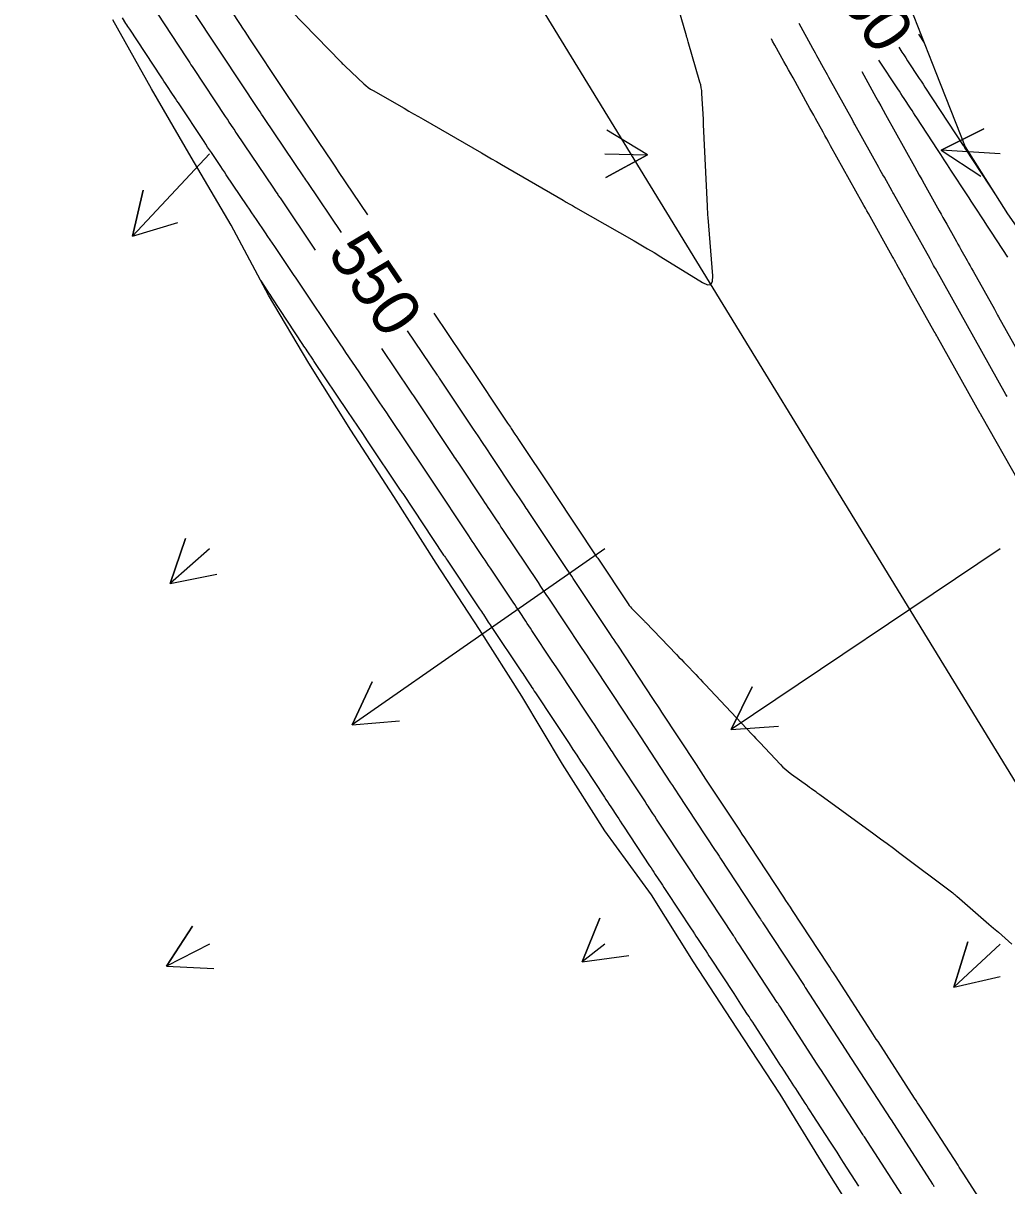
# Model space of a CAD drawing. Extents: x 954385 to 988206, y 1868364 to 1924553.
# Drawn here: x 956633.6 to 956758, y 1921488.4 to 1921635.4 of the extents above; entities that cross this region are included whole.
import ezdxf

# ---------------------------------------------------------------- set-up
doc = ezdxf.new("R2010")
doc.units = 0
for name, color, linetype in [('24', 7, 'Continuous'), ('26', 7, 'Continuous'), ('5', 7, 'Continuous'), ('6', 7, 'Continuous'), ('7', 7, 'Continuous'), ('Default', 7, 'Continuous')]:
    doc.layers.add(name, color=color, linetype=linetype)

msp = doc.modelspace()

# ---------------------------------------------------------------- linework, layer by layer
at = {"layer": '24'}
for points in [[(956745.29, 1921638.69), (956748.99, 1921629.23), (956752.71, 1921619.79), (956758.06, 1921611.33), (956763.82, 1921603.14), (956769.47, 1921594.87), (956775.07, 1921586.57), (956780.57, 1921578.22), (956785.99, 1921569.8), (956791.41, 1921561.4), (956796.82, 1921552.99), (956802.23, 1921544.58), (956807.33, 1921535.97), (956812.17, 1921527.21), (956816.87, 1921518.36), (956821.43, 1921509.43), (956826.18, 1921500.61), (956831.07, 1921491.88), (956835.81, 1921483.05)], [(956739.85, 1921482.96), (956734.55, 1921491.44), (956729.33, 1921499.97), (956723.81, 1921508.32), (956718.33, 1921516.69), (956713.03, 1921525.16), (956707.13, 1921533.28), (956701.77, 1921541.72), (956696.62, 1921550.29), (956691.27, 1921558.74), (956685.8, 1921567.12), (956680.43, 1921575.56), (956675.02, 1921583.97), (956669.7, 1921592.44), (956664.58, 1921601.03), (956659.88, 1921609.88), (956654.82, 1921618.5), (956649.77, 1921627.14), (956644.89, 1921635.87)]]:
    msp.add_lwpolyline(points, dxfattribs=at)
at = {"layer": '26'}
for points in [[(956707.13, 1921618.93), (956712.53, 1921618.8), (956707.27, 1921615.92), (956712.53, 1921618.8), (956707.4, 1921621.92)], [(956757.13, 1921618.93), (956749.68, 1921619.4), (956755.06, 1921622.07), (956749.68, 1921619.4), (956754.68, 1921616.08)], [(956657.13, 1921618.93), (956647.38, 1921608.5), (956648.73, 1921614.34), (956647.38, 1921608.5), (956653.12, 1921610.24)], [(956657.13, 1921568.93), (956652.17, 1921564.58), (956654.1, 1921570.26), (956652.17, 1921564.58), (956658.06, 1921565.75)], [(956707.13, 1921568.93), (956675.17, 1921546.69), (956677.72, 1921552.12), (956675.17, 1921546.69), (956681.15, 1921547.2)], [(956757.13, 1921568.93), (956723.12, 1921546.11), (956725.76, 1921551.5), (956723.12, 1921546.11), (956729.1, 1921546.52)], [(956707.13, 1921518.93), (956704.25, 1921516.68), (956706.5, 1921522.24), (956704.25, 1921516.68), (956710.19, 1921517.51)], [(956657.13, 1921518.93), (956651.69, 1921516.16), (956654.97, 1921521.19), (956651.69, 1921516.16), (956657.69, 1921515.84)], [(956757.13, 1921518.93), (956751.28, 1921513.49), (956753.04, 1921519.22), (956751.28, 1921513.49), (956757.13, 1921514.83)]]:
    msp.add_lwpolyline(points, dxfattribs=at)
at = {"layer": '6'}
for points in [[(956673.82, 1921608.96), (956669.56, 1921615.28), (956669.44, 1921615.47), (956669.31, 1921615.65), (956669.19, 1921615.83), (956669.07, 1921616.02), (956664.1, 1921623.38), (956663.91, 1921623.66), (956663.72, 1921623.95), (956663.53, 1921624.24), (956663.34, 1921624.52), (956658.69, 1921631.53), (956658.44, 1921631.91), (956658.19, 1921632.29), (956657.94, 1921632.67), (956657.69, 1921633.05), (956653.29, 1921639.72)], [(956758.02, 1921588.2), (956757.87, 1921588.46), (956748.95, 1921604.4), (956748.84, 1921604.6), (956748.72, 1921604.81), (956748.44, 1921605.31), (956748.27, 1921605.62), (956743.63, 1921613.92), (956743.57, 1921614.01), (956743.51, 1921614.13), (956743.47, 1921614.19), (956742.49, 1921615.96), (956742.32, 1921616.27), (956742.15, 1921616.57), (956741.98, 1921616.87), (956741.81, 1921617.18), (956738.76, 1921622.64), (956738.69, 1921622.76), (956738.62, 1921622.89), (956738.56, 1921623.01), (956738.49, 1921623.14), (956735.47, 1921628.59), (956735.3, 1921628.9), (956735.13, 1921629.2), (956734.96, 1921629.51), (956734.79, 1921629.82), (956734.12, 1921631.04), (956733.95, 1921631.34), (956733.78, 1921631.65), (956733.61, 1921631.95), (956733.44, 1921632.26), (956731.7, 1921635.41)], [(956744.32, 1921632.4), (956744.71, 1921631.8), (956744.96, 1921631.43), (956745.2, 1921631.06), (956745.44, 1921630.69), (956745.69, 1921630.32), (956746.66, 1921628.84), (956746.9, 1921628.47), (956747.15, 1921628.1), (956747.39, 1921627.73), (956747.63, 1921627.36), (956752.46, 1921619.98), (956752.53, 1921619.88), (956752.61, 1921619.75), (956752.65, 1921619.69), (956752.75, 1921619.53), (956752.77, 1921619.51), (956756.7, 1921613.49)], [(956757.28, 1921482.49), (956752.45, 1921489.97), (956752.29, 1921490.22), (956752.13, 1921490.47), (956751.97, 1921490.72), (956751.81, 1921490.97), (956747.07, 1921498.29), (956746.88, 1921498.58), (956746.69, 1921498.87), (956746.51, 1921499.16), (956746.32, 1921499.45), (956741.69, 1921506.6), (956741.47, 1921506.93), (956741.26, 1921507.26), (956741.04, 1921507.6), (956740.82, 1921507.93), (956736.31, 1921514.91), (956736.06, 1921515.29), (956735.82, 1921515.66), (956735.58, 1921516.04), (956735.33, 1921516.41), (956730.89, 1921523.18), (956730.61, 1921523.61), (956730.33, 1921524.03), (956730.05, 1921524.45), (956729.78, 1921524.87), (956725.46, 1921531.43), (956725.14, 1921531.91), (956724.83, 1921532.38), (956724.52, 1921532.86), (956724.2, 1921533.34), (956719.93, 1921539.82), (956719.63, 1921540.28), (956719.32, 1921540.74), (956719.02, 1921541.2), (956718.72, 1921541.66), (956714.35, 1921548.29), (956714.09, 1921548.69), (956713.82, 1921549.1), (956713.56, 1921549.5), (956713.29, 1921549.9), (956708.76, 1921556.76), (956708.53, 1921557.1), (956708.3, 1921557.44), (956708.08, 1921557.78), (956707.85, 1921558.13), (956703.12, 1921565.21), (956702.94, 1921565.49), (956702.75, 1921565.77), (956702.57, 1921566.05), (956702.38, 1921566.33), (956697.48, 1921573.67), (956697.34, 1921573.88), (956697.2, 1921574.1), (956697.06, 1921574.31), (956696.91, 1921574.52), (956696.34, 1921575.38), (956696.06, 1921575.81), (956695.77, 1921576.24), (956692.75, 1921580.77), (956692.2, 1921581.6), (956691.65, 1921582.42), (956691.1, 1921583.25), (956690.54, 1921584.07), (956686.22, 1921590.55), (956686.15, 1921590.64), (956686.08, 1921590.74), (956686.02, 1921590.84), (956685.95, 1921590.94), (956682.19, 1921596.52)]]:
    msp.add_lwpolyline(points, dxfattribs=at)
at = {"layer": '7'}
for points in [[(956667.45, 1921637.02), (956673.78, 1921630.5), (956673.9, 1921630.37), (956674.02, 1921630.25), (956674.14, 1921630.14), (956674.27, 1921630.02), (956676.64, 1921627.79), (956676.92, 1921627.55), (956677.21, 1921627.32), (956677.51, 1921627.11), (956677.83, 1921626.92), (956681.74, 1921624.68), (956682.34, 1921624.34), (956682.95, 1921623.99), (956683.55, 1921623.64), (956684.15, 1921623.3), (956691.55, 1921619.03), (956692.18, 1921618.67), (956692.81, 1921618.3), (956693.44, 1921617.94), (956694.07, 1921617.57), (956701.86, 1921613.05), (956702.25, 1921612.82), (956702.64, 1921612.6), (956703.03, 1921612.37), (956703.42, 1921612.15), (956710.85, 1921607.9), (956711.7, 1921607.42), (956712.54, 1921606.92), (956713.38, 1921606.42), (956714.21, 1921605.91), (956719.47, 1921602.65), (956720.11, 1921602.36), (956720.54, 1921602.4), (956720.77, 1921602.77), (956720.8, 1921603.47), (956720.2, 1921610.85), (956720.17, 1921611.22), (956720.15, 1921611.58), (956720.13, 1921611.94), (956720.11, 1921612.31), (956719.63, 1921622.65), (956719.62, 1921622.81), (956719.61, 1921622.98), (956719.61, 1921623.15), (956719.6, 1921623.31), (956719.42, 1921626.55), (956719.39, 1921626.92), (956719.34, 1921627.28), (956719.27, 1921627.64), (956719.17, 1921628), (956717.69, 1921633.07), (956717.63, 1921633.26), (956717.57, 1921633.45), (956717.52, 1921633.65), (956717.46, 1921633.84), (956714.92, 1921642.57)], [(956656.6, 1921641.97), (956661.01, 1921635.27), (956661.31, 1921634.83), (956661.6, 1921634.38), (956661.9, 1921633.93), (956662.2, 1921633.49), (956666.44, 1921627.08), (956666.79, 1921626.56), (956667.13, 1921626.04), (956667.48, 1921625.52), (956667.83, 1921625), (956672.02, 1921618.78), (956672.37, 1921618.26), (956672.72, 1921617.74), (956673.07, 1921617.22), (956673.42, 1921616.7), (956677.13, 1921611.19)], [(956649.69, 1921637.93), (956653.16, 1921632.66), (956653.32, 1921632.42), (956653.48, 1921632.17), (956653.65, 1921631.93), (956653.81, 1921631.68), (956654.46, 1921630.7), (956654.62, 1921630.45), (956654.78, 1921630.2), (956654.94, 1921629.96), (956655.11, 1921629.71), (956659.12, 1921623.66), (956659.23, 1921623.48), (956659.35, 1921623.3), (956659.47, 1921623.12), (956659.59, 1921622.94), (956660.07, 1921622.22), (956660.19, 1921622.04), (956660.31, 1921621.86), (956660.43, 1921621.68), (956660.55, 1921621.5), (956665.14, 1921614.69), (956665.29, 1921614.46), (956665.44, 1921614.24), (956665.75, 1921613.79), (956665.82, 1921613.67), (956665.9, 1921613.56), (956665.98, 1921613.45), (956666.05, 1921613.34), (956670.5, 1921606.73)], [(956745.11, 1921486.59), (956739.97, 1921494.54), (956739.87, 1921494.69), (956739.77, 1921494.85), (956734.44, 1921503.08), (956734.41, 1921503.13), (956734.01, 1921503.75), (956729.25, 1921511.09), (956729.15, 1921511.25), (956729.05, 1921511.41), (956729.02, 1921511.45), (956729, 1921511.49), (956728.97, 1921511.53), (956728.94, 1921511.57), (956724.08, 1921518.98), (956723.97, 1921519.16), (956723.85, 1921519.33), (956723.62, 1921519.68), (956723.57, 1921519.77), (956723.51, 1921519.85), (956723.45, 1921519.94), (956723.39, 1921520.03), (956718.88, 1921526.88), (956718.62, 1921527.28), (956718.18, 1921527.94), (956718.09, 1921528.08), (956718.01, 1921528.21), (956717.92, 1921528.34), (956717.83, 1921528.48), (956713.69, 1921534.76), (956713.45, 1921535.12), (956713.21, 1921535.48), (956712.74, 1921536.2), (956712.62, 1921536.38), (956712.5, 1921536.56), (956712.38, 1921536.74), (956712.26, 1921536.93), (956708.36, 1921542.85), (956708.22, 1921543.06), (956708.09, 1921543.27), (956707.95, 1921543.47), (956707.81, 1921543.68), (956707.27, 1921544.51), (956707.13, 1921544.71), (956707, 1921544.92), (956706.86, 1921545.13), (956706.73, 1921545.33), (956705.82, 1921546.71), (956705.52, 1921547.16), (956702.46, 1921551.78), (956701.97, 1921552.52), (956701.48, 1921553.27), (956700.98, 1921554.01), (956700.49, 1921554.75), (956697.92, 1921558.61), (956697.72, 1921558.91), (956697.52, 1921559.21), (956697.32, 1921559.5), (956697.12, 1921559.8), (956696.33, 1921561), (956696.13, 1921561.3), (956695.93, 1921561.59), (956695.73, 1921561.89), (956695.53, 1921562.19), (956692.66, 1921566.49), (956692.43, 1921566.83), (956692.2, 1921567.18), (956691.98, 1921567.52), (956691.75, 1921567.86), (956690.83, 1921569.23), (956690.6, 1921569.58), (956690.37, 1921569.92), (956690.15, 1921570.26), (956689.92, 1921570.61), (956685.33, 1921577.49), (956685.08, 1921577.87), (956684.82, 1921578.25), (956684.57, 1921578.63), (956684.32, 1921579.01), (956679.84, 1921585.71), (956679.55, 1921586.14), (956679.26, 1921586.57), (956678.97, 1921587), (956678.68, 1921587.43), (956677.33, 1921589.43), (956677.01, 1921589.91), (956676.69, 1921590.38), (956676.37, 1921590.86), (956676.05, 1921591.34), (956674.39, 1921593.79), (956674.03, 1921594.33), (956673.67, 1921594.87), (956673.31, 1921595.4), (956672.94, 1921595.94), (956668.75, 1921602.17), (956668.42, 1921602.67), (956668.08, 1921603.17), (956667.74, 1921603.67), (956667.4, 1921604.17), (956665.37, 1921607.19), (956665.08, 1921607.62), (956664.79, 1921608.05), (956664.51, 1921608.48), (956664.22, 1921608.91), (956663.06, 1921610.62), (956662.78, 1921611.05), (956662.49, 1921611.47), (956662.2, 1921611.9), (956661.91, 1921612.33), (956659.25, 1921616.28), (956659.01, 1921616.63), (956658.78, 1921616.98), (956658.54, 1921617.33), (956658.31, 1921617.68), (956657.36, 1921619.07), (956657.13, 1921619.42), (956656.89, 1921619.77), (956656.66, 1921620.13), (956656.43, 1921620.48), (956653.19, 1921625.36), (956653.01, 1921625.64), (956652.83, 1921625.91), (956652.65, 1921626.19), (956652.46, 1921626.46), (956651.73, 1921627.57), (956651.55, 1921627.84), (956651.37, 1921628.12), (956651.19, 1921628.39), (956651.01, 1921628.67), (956647.03, 1921634.7), (956646.92, 1921634.87), (956646.8, 1921635.05), (956646.68, 1921635.23), (956646.56, 1921635.41), (956646.1, 1921636.12)], [(956746.82, 1921634.05), (956747.52, 1921632.98)], [(956759.45, 1921577.53), (956754.87, 1921585.64), (956754.81, 1921585.75), (956754.75, 1921585.86), (956754.69, 1921585.97), (956754.62, 1921586.08), (956749.23, 1921595.72), (956749.13, 1921595.9), (956749.02, 1921596.09), (956748.92, 1921596.28), (956748.81, 1921596.46), (956745.27, 1921602.79), (956745.12, 1921603.06), (956744.97, 1921603.33), (956744.82, 1921603.59), (956744.68, 1921603.86), (956744.08, 1921604.92), (956743.93, 1921605.19), (956743.78, 1921605.45), (956743.63, 1921605.72), (956743.49, 1921605.99), (956740.47, 1921611.37), (956740.28, 1921611.71), (956740.09, 1921612.06), (956739.89, 1921612.4), (956739.7, 1921612.75), (956735.69, 1921619.94), (956735.45, 1921620.37), (956735.21, 1921620.8), (956734.97, 1921621.23), (956734.74, 1921621.66), (956733.78, 1921623.38), (956733.55, 1921623.81), (956733.31, 1921624.24), (956733.07, 1921624.67), (956732.83, 1921625.1), (956730.94, 1921628.52), (956730.65, 1921629.04), (956730.37, 1921629.56), (956730.08, 1921630.08), (956729.79, 1921630.6), (956728.64, 1921632.67), (956728.36, 1921633.19), (956728.2, 1921633.47)], [(956758.11, 1921605.83), (956756.05, 1921609), (956755.53, 1921609.79), (956755.02, 1921610.58), (956753.99, 1921612.16), (956753.73, 1921612.55), (956753.47, 1921612.95), (956753.22, 1921613.34), (956752.96, 1921613.73), (956750.92, 1921616.86), (956750.49, 1921617.51), (956750.06, 1921618.16), (956749.64, 1921618.82), (956749.21, 1921619.47), (956746.59, 1921623.48), (956746.39, 1921623.79), (956746.19, 1921624.09), (956745.99, 1921624.4), (956745.79, 1921624.7), (956744.99, 1921625.93), (956744.79, 1921626.23), (956744.59, 1921626.54), (956744.39, 1921626.84), (956744.19, 1921627.15), (956741.81, 1921630.76)], [(956739.63, 1921629.32), (956741.43, 1921626.07), (956741.73, 1921625.52), (956742.04, 1921624.98), (956742.34, 1921624.43), (956742.64, 1921623.88), (956746.3, 1921617.33), (956746.61, 1921616.78), (956746.91, 1921616.24), (956747.22, 1921615.69), (956747.52, 1921615.14), (956749.44, 1921611.71), (956749.68, 1921611.29), (956749.91, 1921610.87), (956750.15, 1921610.45), (956750.39, 1921610.03), (956751.41, 1921608.19), (956751.61, 1921607.84), (956751.8, 1921607.5), (956751.99, 1921607.16), (956752.18, 1921606.82), (956752.95, 1921605.44), (956753.14, 1921605.1), (956753.33, 1921604.76), (956753.52, 1921604.42), (956753.72, 1921604.07), (956756.41, 1921599.25), (956756.55, 1921599.01), (956756.68, 1921598.77), (956756.82, 1921598.53), (956756.95, 1921598.28), (956761.41, 1921590.32)], [(956663.62, 1921602.84), (956664.46, 1921601.56), (956664.6, 1921601.34), (956664.74, 1921601.13), (956664.88, 1921600.92), (956665.02, 1921600.7), (956668.9, 1921594.8), (956669.03, 1921594.6), (956669.17, 1921594.39), (956669.3, 1921594.19), (956669.44, 1921593.99), (956670.24, 1921592.8), (956670.27, 1921592.76), (956670.33, 1921592.66), (956674.6, 1921586.33), (956675.23, 1921585.4), (956675.85, 1921584.48), (956676.47, 1921583.55), (956677.09, 1921582.63), (956681.26, 1921576.39), (956681.34, 1921576.28), (956681.41, 1921576.16), (956681.49, 1921576.05), (956681.57, 1921575.93), (956686.74, 1921568.16), (956686.85, 1921568), (956686.96, 1921567.83), (956687.07, 1921567.67), (956687.18, 1921567.51), (956691.27, 1921561.37), (956691.39, 1921561.19), (956691.52, 1921561), (956691.64, 1921560.81), (956691.77, 1921560.63), (956692.27, 1921559.88), (956692.39, 1921559.69), (956692.51, 1921559.51), (956692.64, 1921559.32), (956692.76, 1921559.13), (956696.59, 1921553.39), (956696.74, 1921553.17), (956696.89, 1921552.95), (956697.04, 1921552.73), (956697.18, 1921552.51), (956697.77, 1921551.62), (956697.92, 1921551.4), (956698.07, 1921551.18), (956698.21, 1921550.96), (956698.36, 1921550.74), (956699.36, 1921549.23), (956699.68, 1921548.74), (956702.61, 1921544.31), (956703.1, 1921543.57), (956703.59, 1921542.83), (956704.07, 1921542.09), (956704.56, 1921541.35), (956707.08, 1921537.53), (956707.28, 1921537.22), (956707.48, 1921536.92), (956707.68, 1921536.61), (956707.88, 1921536.31), (956708.69, 1921535.09), (956708.89, 1921534.78), (956709.09, 1921534.48), (956709.29, 1921534.17), (956709.49, 1921533.87), (956712.8, 1921528.84), (956712.98, 1921528.57), (956713.16, 1921528.3), (956713.34, 1921528.02), (956713.52, 1921527.75), (956714.24, 1921526.67), (956714.41, 1921526.39), (956714.59, 1921526.12), (956714.77, 1921525.85), (956714.95, 1921525.58), (956718.05, 1921520.87), (956718.26, 1921520.56), (956718.46, 1921520.25), (956718.66, 1921519.94), (956718.87, 1921519.63), (956719.69, 1921518.39), (956719.89, 1921518.08), (956720.1, 1921517.77), (956720.3, 1921517.45), (956720.5, 1921517.14), (956723.44, 1921512.67), (956723.65, 1921512.35), (956723.87, 1921512.02), (956724.08, 1921511.69), (956724.29, 1921511.36), (956725.15, 1921510.05), (956725.37, 1921509.73), (956725.58, 1921509.4), (956725.8, 1921509.07), (956726.01, 1921508.74), (956728.86, 1921504.34), (956729.08, 1921504.01), (956729.29, 1921503.67), (956729.51, 1921503.34), (956729.72, 1921503.01), (956730.59, 1921501.67), (956730.8, 1921501.34), (956731.02, 1921501), (956731.24, 1921500.67), (956731.45, 1921500.33), (956732.43, 1921498.82), (956732.67, 1921498.46), (956732.9, 1921498.09), (956733.14, 1921497.73), (956733.37, 1921497.37), (956735.63, 1921493.88), (956736.04, 1921493.24), (956736.46, 1921492.6), (956736.87, 1921491.97), (956737.28, 1921491.33), (956739.23, 1921488.31)], [(956685.51, 1921598.75), (956689.13, 1921593.38), (956689.31, 1921593.1), (956689.5, 1921592.83), (956689.68, 1921592.55), (956689.87, 1921592.28), (956694.83, 1921584.86), (956694.94, 1921584.68), (956695.06, 1921584.51), (956695.18, 1921584.34), (956695.29, 1921584.16), (956695.76, 1921583.46), (956695.99, 1921583.11), (956696.22, 1921582.76), (956700.46, 1921576.41), (956700.54, 1921576.29), (956700.61, 1921576.18), (956700.68, 1921576.07), (956700.76, 1921575.96), (956706.1, 1921567.95), (956706.16, 1921567.86), (956706.23, 1921567.76), (956710.09, 1921561.97), (956710.22, 1921561.78), (956710.36, 1921561.6), (956710.51, 1921561.43), (956710.66, 1921561.27), (956712.02, 1921559.92), (956712.08, 1921559.86), (956712.14, 1921559.79), (956712.21, 1921559.73), (956712.27, 1921559.66), (956716.21, 1921555.56), (956716.51, 1921555.25), (956716.82, 1921554.93), (956717.12, 1921554.62), (956717.42, 1921554.3), (956718.63, 1921553.04), (956718.94, 1921552.73), (956719.24, 1921552.41), (956719.54, 1921552.09), (956719.84, 1921551.77), (956725.73, 1921545.5), (956725.98, 1921545.23), (956726.23, 1921544.97), (956726.48, 1921544.7), (956726.73, 1921544.43), (956729.35, 1921541.66), (956729.67, 1921541.33), (956730.01, 1921541.02), (956730.37, 1921540.72), (956730.74, 1921540.44), (956732.75, 1921538.99), (956733.01, 1921538.8), (956733.28, 1921538.61), (956733.81, 1921538.23), (956733.94, 1921538.14), (956734.07, 1921538.04), (956734.2, 1921537.94), (956734.34, 1921537.85), (956741.18, 1921532.87), (956742.01, 1921532.27), (956742.83, 1921531.67), (956743.64, 1921531.06), (956744.46, 1921530.45), (956751.15, 1921525.41), (956751.28, 1921525.31), (956751.41, 1921525.2), (956751.54, 1921525.1), (956751.67, 1921524.99), (956755.72, 1921521.46), (956756.31, 1921520.94), (956756.91, 1921520.43), (956758.62, 1921518.93)], [(956678.88, 1921594.28), (956682.51, 1921588.9), (956682.59, 1921588.78), (956682.67, 1921588.65), (956682.76, 1921588.53), (956682.84, 1921588.41), (956687.94, 1921580.77), (956688.09, 1921580.55), (956688.24, 1921580.34), (956688.38, 1921580.12), (956688.53, 1921579.9), (956691.71, 1921575.13), (956691.91, 1921574.82), (956692.12, 1921574.51), (956692.33, 1921574.19), (956692.54, 1921573.88), (956693.37, 1921572.63), (956693.58, 1921572.32), (956693.79, 1921572.01), (956693.99, 1921571.7), (956694.2, 1921571.38), (956698.68, 1921564.67), (956699.01, 1921564.17), (956699.34, 1921563.68), (956699.67, 1921563.19), (956700, 1921562.7), (956704.16, 1921556.45), (956704.52, 1921555.9), (956704.89, 1921555.35), (956705.25, 1921554.8), (956705.62, 1921554.26), (956709.82, 1921547.9), (956710.12, 1921547.45), (956710.41, 1921547.01), (956710.7, 1921546.56), (956711, 1921546.12), (956715.45, 1921539.35), (956715.68, 1921539), (956715.91, 1921538.65), (956716.14, 1921538.3), (956716.37, 1921537.96), (956721.09, 1921530.8), (956721.25, 1921530.55), (956721.42, 1921530.3), (956721.58, 1921530.05), (956721.75, 1921529.79), (956726.71, 1921522.26), (956726.82, 1921522.1), (956726.92, 1921521.94), (956727.02, 1921521.78), (956727.13, 1921521.63), (956732.33, 1921513.69), (956732.37, 1921513.63), (956732.41, 1921513.58), (956732.45, 1921513.52), (956732.48, 1921513.46), (956737.54, 1921505.65), (956737.85, 1921505.17), (956743.22, 1921496.87), (956743.31, 1921496.74), (956743.34, 1921496.69), (956748.6, 1921488.56), (956748.66, 1921488.47), (956748.71, 1921488.38), (956748.77, 1921488.29)]]:
    msp.add_lwpolyline(points, dxfattribs=at)
at = {"layer": 'Default'}
msp.add_line((957221.14, 1920784.24), (956045.8, 1922705.18), dxfattribs=at)

# ---------------------------------------------------------------- texts
at = {"layer": '5'}
for rotation, p in [(303.3336, (956734.16, 1921642.39)), (303.9458, (956671.93, 1921606.4))]:
    msp.add_text('550', height=6, rotation=rotation, dxfattribs=at).set_placement(p)

doc.saveas('drawing.dxf')
